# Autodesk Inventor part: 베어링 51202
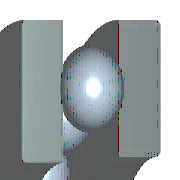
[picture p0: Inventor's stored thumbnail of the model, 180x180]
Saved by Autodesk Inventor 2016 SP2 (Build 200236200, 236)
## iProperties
Created: 2012-02
Part Number: 베어링 51202
Material: 강철, 연강
Description: 롤링 베어링 - 플랫 뒷면이 있는 스러스트 볼 베어링
Document SubType Name: Modeling
Standard: KS B 2022
Designer: mduedu
Standards Organization: KS
Language: ko-KR
Size Designation: 51202 - 15 x 32 x 12
Categories: <MemberInstance><Categories><Category DisplayName="샤프트 부품" InternalName="7f7aeb1f-a693-4053-b835-cee3144e0d98" Mnemonic="SHFT"><Category DisplayName="베어링" Inter
Density: 1 g/cm^3
Appearance: 진녹색
IsCustomPart: 1
Author: mduedu
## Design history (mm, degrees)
sketch "스케치1" dims "d3" = 5.28 (= 0.44 x KB)
  geometry: L1 (6, 9.61)-(6, 14.89); L2 (8.64, 12.25)-(3.36, 12.25); L3 (3.6, 16)-(0, 16); L4 (3.6, 7.5)-(0, 7.5); L5 (8.4, 13.35)-(8.4, 16); L6 (8.4, 16)-(12, 16); L7 (12, 16)-(12, 8.5); L8 (12, 8.5)-(8.4, 8.5); L9 (8.4, 8.5)-(8.4, 11.15); L10 (3.6, 16)-(3.6, 13.35); L11 (3.6, 11.15)-(3.6, 7.5); L12 (-1.8, 0)-(10.8, 0) reference; L13 (0, -0.022)-(0, 5.522) reference; 1 further point
  constraints: 22 end point, 5 perpendicular, 2 equal length, 2 midpoint, 2 parallel, 2 point on line, 1 collinear, 10 other
  dimensions: "d8" = 4.8 diameter of L11 L1 (= 0.4 x KB); "d11" = 15 diameter of L4 L12 (= WD); "d12" = 17 diameter of L8 L12 (= KAD1); "d13" = 32 diameter of L3 L12 (= KID1); "d14" = 32 diameter of L6 L12 (= BD); "d15" = 24.5 diameter of point (6, 12.25) L12 (= 0.5 x KID1 + 0.5 x KAD1); "d16" = 6 distance from line of point (6, 12.25) L13 (= 0.5 x KB); "d18" = 12 distance between parallel lines of L7 L13 (= KB)
revolve "본체" stored, may be unused: angle "d9" = 90 deg
revolve "볼" stored, may be unused: angle "d10" = 90 deg
pattern_circular "IDS_ARRAYBALL[SIMPL:T]" dims angle "d2" = 360 deg
body "Solid1"
fillet "모깎기1" dims "d4" = 0.6 (= KRS)
fillet "모깎기2" dims "d5" = 0.6 (= KRS)
other parameters: "WD" = 15 [user parameter; used in 2 equation terms], "KAD1" = 17 [user parameter; used in 3 equation terms], "KID1" = 32 [user parameter; used in 3 equation terms], "BD" = 32 [user parameter; used in 2 equation terms], "KB" = 12 [user parameter; used in 6 equation terms], "KRS" = 0.6 [user parameter; used in 2 equation terms], "d0" = 2.4 (= 0.2 x KB), "d6" = 0, "d7" = 0, "d19" = 0, "d41" = 0, "d42" = 0, "WR" = 7.5 (= 0.5 x WD) [user parameter], "BC" = 1.65e+07 [user parameter], "BBA" = 90 deg [user parameter], "BC0" = 2.7e+07 [user parameter], "BR" = 16 (= 0.5 x BD) [user parameter]
